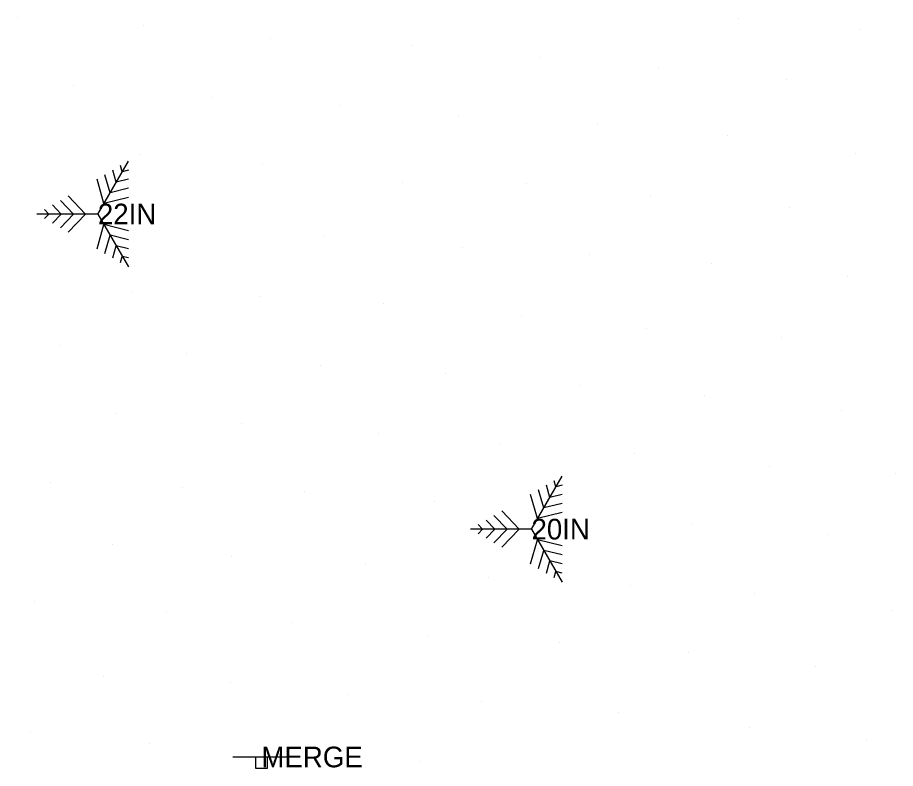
# Model space of a CAD drawing. Extents: x 1732346 to 1733076, y 467730 to 468633.
# Drawn here: x 1732602.3 to 1732678.7, y 468123.1 to 468188.4 of the extents above; entities that cross this region are included whole.
import ezdxf

# ---------------------------------------------------------------- set-up
doc = ezdxf.new("R2010")
doc.units = 0
for name, color, linetype in [('Default', 7, 'Continuous'), ('S_Ground_SpotElevation', 7, 'Continuous'), ('S_Text', 7, 'Continuous'), ('S_Traffic_Sign_SinglePost', 7, 'Continuous'), ('S_Trees_Conifer_Pay', 7, 'Continuous')]:
    doc.layers.add(name, color=color, linetype=linetype)

# ---------------------------------------------------------------- blocks, each defined once
blk = doc.blocks.new('POINT_DISPLAY')
at = {"layer": 'Default'}
blk.add_line((0, 0), (0, 0), dxfattribs=at)

msp = doc.modelspace()

# ---------------------------------------------------------------- linework, layer by layer
at = {"layer": 'S_Traffic_Sign_SinglePost'}
msp.add_line((1732621.025, 468124.05), (1732626.015, 468124.05), dxfattribs=at)
msp.add_lwpolyline([(1732623.021, 468124.05), (1732624.019, 468124.05), (1732624.019, 468123.052), (1732623.021, 468123.052)], close=True, dxfattribs=at)
at = {"layer": 'S_Trees_Conifer_Pay'}
for p, q in [((1732609.278, 468171.333), (1732611.941, 468175.944)), ((1732610.873, 468174.097), (1732610.572, 468175.153)), ((1732611.407, 468175.021), (1732611.257, 468175.55)), ((1732611.941, 468175.153), (1732611.407, 468175.021)), ((1732609.81, 468172.256), (1732609.203, 468174.362)), ((1732610.344, 468173.177), (1732609.887, 468174.756)), ((1732611.941, 468174.362), (1732610.873, 468174.097)), ((1732611.941, 468173.574), (1732610.344, 468173.177)), ((1732608.212, 468171.333), (1732606.692, 468172.915)), ((1732611.941, 468172.78), (1732609.81, 468172.256)), ((1732606.083, 468171.333), (1732605.323, 468172.121)), ((1732607.149, 468171.333), (1732606.008, 468172.518)), ((1732609.278, 468171.333), (1732603.954, 468171.333)), ((1732605.017, 468171.333), (1732604.639, 468171.727)), ((1732604.639, 468170.939), (1732605.017, 468171.333)), ((1732605.323, 468170.542), (1732606.083, 468171.333)), ((1732606.008, 468170.145), (1732607.149, 468171.333)), ((1732606.692, 468169.751), (1732608.212, 468171.333)), ((1732609.278, 468171.333), (1732611.941, 468166.722)), ((1732609.203, 468168.304), (1732609.81, 468170.41)), ((1732611.941, 468169.883), (1732609.81, 468170.41)), ((1732609.887, 468167.907), (1732610.344, 468169.487)), ((1732611.941, 468169.092), (1732610.344, 468169.487)), ((1732610.572, 468167.51), (1732610.873, 468168.566)), ((1732611.941, 468168.304), (1732610.873, 468168.566)), ((1732611.257, 468167.116), (1732611.407, 468167.645)), ((1732611.941, 468167.51), (1732611.407, 468167.645)), ((1732647.047, 468143.891), (1732649.71, 468148.502)), ((1732649.176, 468147.579), (1732649.026, 468148.108)), ((1732648.113, 468145.735), (1732647.656, 468147.314)), ((1732648.642, 468146.655), (1732648.341, 468147.711)), ((1732649.71, 468147.711), (1732649.176, 468147.579)), ((1732647.579, 468144.814), (1732646.972, 468146.92)), ((1732649.71, 468146.92), (1732648.642, 468146.655)), ((1732649.71, 468146.132), (1732648.113, 468145.735)), ((1732644.918, 468143.891), (1732643.777, 468145.076)), ((1732645.981, 468143.891), (1732644.461, 468145.473)), ((1732649.71, 468145.338), (1732647.579, 468144.814)), ((1732642.786, 468143.891), (1732642.408, 468144.285)), ((1732643.852, 468143.891), (1732643.092, 468144.679)), ((1732647.047, 468143.891), (1732641.723, 468143.891)), ((1732642.408, 468143.497), (1732642.786, 468143.891)), ((1732643.092, 468143.1), (1732643.852, 468143.891)), ((1732643.777, 468142.703), (1732644.918, 468143.891)), ((1732644.461, 468142.309), (1732645.981, 468143.891)), ((1732647.047, 468143.891), (1732649.71, 468139.28)), ((1732646.972, 468140.862), (1732647.579, 468142.968)), ((1732649.71, 468142.441), (1732647.579, 468142.968)), ((1732647.656, 468140.465), (1732648.113, 468142.045)), ((1732649.71, 468141.65), (1732648.113, 468142.045)), ((1732648.341, 468140.068), (1732648.642, 468141.124)), ((1732649.71, 468140.862), (1732648.642, 468141.124)), ((1732649.026, 468139.674), (1732649.176, 468140.203)), ((1732649.71, 468140.068), (1732649.176, 468140.203))]:
    msp.add_line(p, q, dxfattribs=at)

# ---------------------------------------------------------------- block references
at = {"layer": 'S_Ground_SpotElevation'}
for p in [(1732602.282, 468188.444), (1732665.093, 468188.337), (1732613.249, 468187.757), (1732675.694, 468187.37), (1732624.282, 468186.66), (1732636.593, 468186.035), (1732647.76, 468184.95), (1732658.08, 468184.047), (1732607.152, 468182.535), (1732669.256, 468183.056), (1732619.222, 468181.495), (1732630.452, 468180.811), (1732640.702, 468179.814), (1732652.837, 468179.173), (1732664.111, 468178.137), (1732613.022, 468176.559), (1732675.23, 468176.571), (1732623.58, 468175.718), (1732635.776, 468174.07), (1732646.607, 468173.994), (1732657.399, 468172.97), (1732669.56, 468171.928), (1732607.24, 468170.438), (1732628.936, 468169.5), (1732641.022, 468168.428), (1732652.061, 468167.845), (1732662.691, 468167.023), (1732674.528, 468165.851), (1732612.333, 468164.569), (1732623.455, 468164.185), (1732634.124, 468163.553), (1732646.185, 468162.451), (1732657.023, 468161.378), (1732668.798, 468160.615), (1732605.949, 468159.873), (1732616.996, 468159.173), (1732628.709, 468158.171), (1732639.573, 468157.466), (1732651.199, 468156.4), (1732662.086, 468155.53), (1732674.004, 468154.258), (1732610.855, 468153.966), (1732621.751, 468153.097), (1732633.724, 468152.219), (1732644.31, 468151.299), (1732656.024, 468150.478), (1732667.803, 468149.364), (1732678.744, 468148.759), (1732605.158, 468147.95), (1732616.608, 468147.551), (1732627.283, 468147.143), (1732638.627, 468146.282), (1732649.843, 468144.345), (1732661.076, 468144.376), (1732672.908, 468143.441), (1732610.549, 468142.518), (1732620.942, 468141.485), (1732632.617, 468140.924), (1732643.317, 468139.706), (1732655.644, 468138.968), (1732666.455, 468138.285), (1732603.735, 468137.584), (1732615.259, 468136.605), (1732678.437, 468136.781), (1732626.131, 468135.776), (1732638, 468134.595), (1732649.466, 468134.01), (1732660.756, 468133.134), (1732671.819, 468131.957), (1732609.758, 468131.049), (1732620.795, 468130.558), (1732631.149, 468129.505), (1732642.667, 468128.842), (1732654.615, 468127.892), (1732603.443, 468126.252), (1732666.068, 468126.606), (1732613.756, 468125.19), (1732676.247, 468125.569), (1732625.677, 468124.537), (1732637.31, 468123.621)]:
    msp.add_blockref('POINT_DISPLAY', p, dxfattribs=at)

# ---------------------------------------------------------------- texts
at = {"layer": 'S_Text'}
for s, p in [('22IN', (1732609.278, 468170.433)), ('20IN', (1732647.047, 468142.991)), ('MERGE', (1732623.52, 468123.15))]:
    msp.add_text(s, height=1.8, dxfattribs=at).set_placement(p)

doc.saveas('drawing.dxf')
